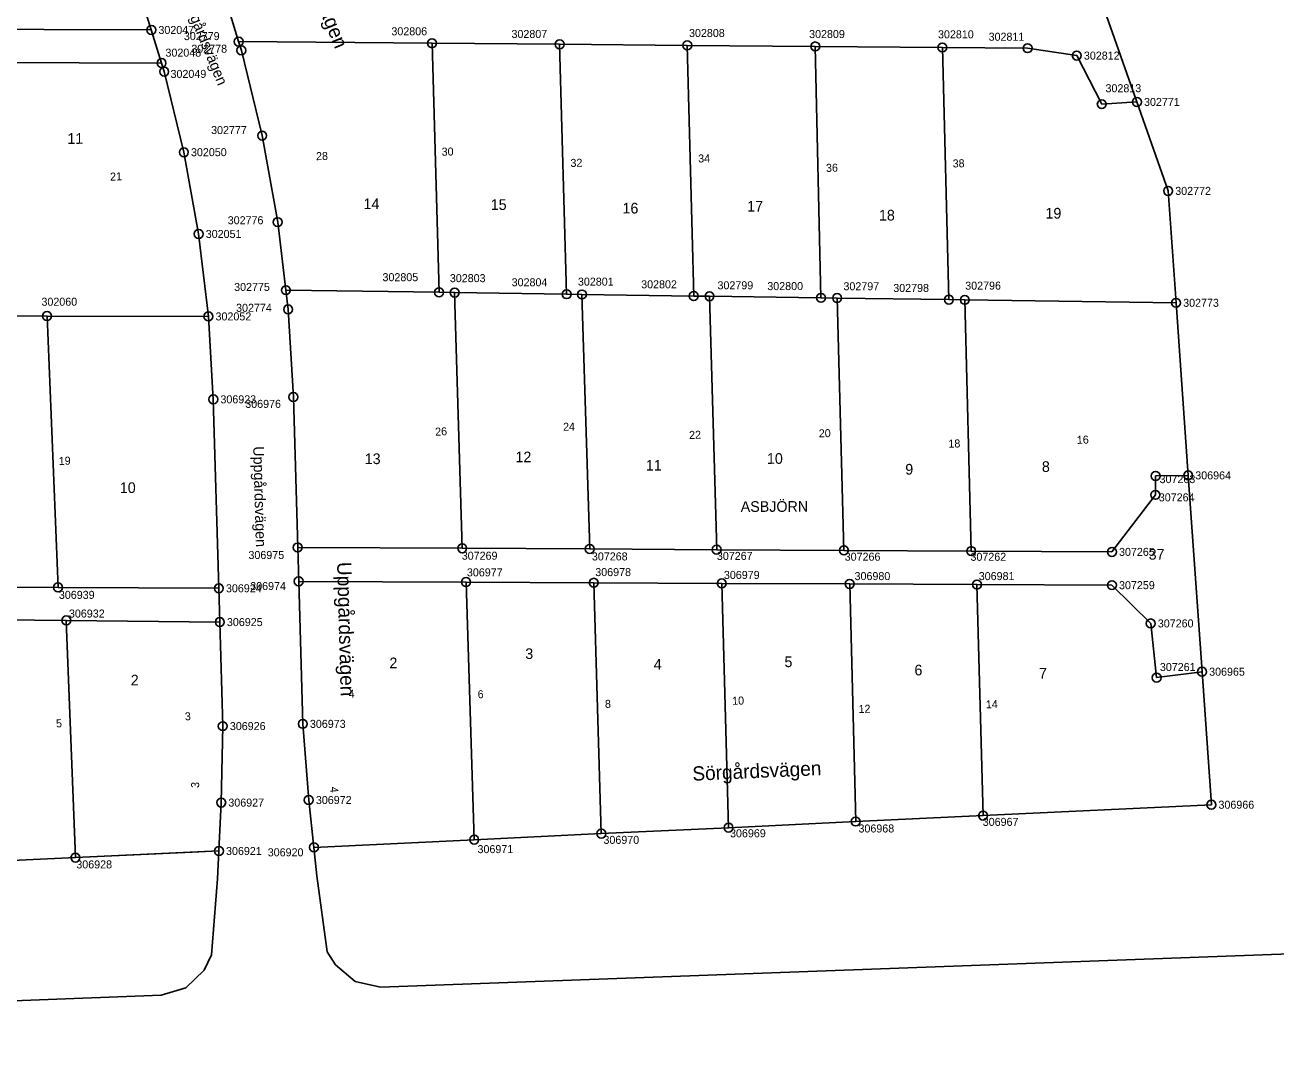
# Model space of a CAD drawing. Extents: x 141995 to 152570, y 6580184 to 6586000.
# Drawn here: x 142587.1 to 142727.8, y 6585369.2 to 6585483.5 of the extents above; entities that cross this region are included whole.
import ezdxf

# ---------------------------------------------------------------- set-up
doc = ezdxf.new("R2010")
doc.units = 0
for name, color, linetype in [('Level 10', 7, 'Continuous'), ('Level 13', 7, 'Continuous'), ('Level 40', 7, 'Continuous'), ('Level 42', 7, 'Continuous'), ('Level 43', 7, 'Continuous'), ('Level 5', 7, 'Continuous'), ('Level 51', 7, 'Continuous'), ('Level 53', 7, 'Continuous'), ('Level 54', 7, 'Continuous'), ('Level 55', 7, 'Continuous'), ('Level 58', 7, 'Continuous'), ('Level 6', 7, 'Continuous'), ('Level 7', 7, 'Continuous')]:
    doc.layers.add(name, color=color, linetype=linetype)

msp = doc.modelspace()

# ---------------------------------------------------------------- linework, layer by layer
at = {"layer": 'Level 10'}
for centre in [(142601.32, 6585482.97), (142611.14, 6585481.66), (142611.44, 6585480.68), (142632.88, 6585481.48), (142647.22, 6585481.36), (142661.57, 6585481.24), (142675.96, 6585481.12), (142690.25, 6585481), (142699.83, 6585480.92), (142602.47, 6585479.25), (142705.36, 6585480.09), (142602.77, 6585478.29), (142712.12, 6585474.88), (142708.17, 6585474.63), (142613.78, 6585471.09), (142604.98, 6585469.22), (142715.63, 6585464.88), (142615.53, 6585461.37), (142606.64, 6585460.04), (142616.45, 6585453.72), (142633.67, 6585453.48), (142635.42, 6585453.45), (142648.01, 6585453.27), (142649.73, 6585453.24), (142662.3, 6585453.06), (142664.07, 6585453.04), (142676.6, 6585452.86), (142678.42, 6585452.84), (142690.98, 6585452.66), (142692.77, 6585452.63), (142716.52, 6585452.3), (142616.7, 6585451.56), (142589.6, 6585450.81), (142607.74, 6585450.77), (142608.29, 6585441.45), (142617.29, 6585441.71), (142714.22, 6585432.84), (142717.88, 6585432.9), (142714.2, 6585430.71), (142617.78, 6585424.8), (142636.27, 6585424.71), (142650.61, 6585424.63), (142664.88, 6585424.55), (142679.18, 6585424.47), (142693.49, 6585424.39), (142709.31, 6585424.3), (142590.83, 6585420.31), (142608.91, 6585420.21), (142617.89, 6585420.99), (142636.7, 6585420.91), (142651.06, 6585420.83), (142665.45, 6585420.76), (142679.83, 6585420.7), (142694.14, 6585420.63), (142709.31, 6585420.56), (142591.76, 6585416.6), (142609.02, 6585416.41), (142713.67, 6585416.26), (142714.33, 6585410.17), (142719.44, 6585410.83), (142609.35, 6585404.71), (142618.35, 6585404.97), (142609.18, 6585396.12), (142619.02, 6585396.41), (142694.83, 6585394.66), (142720.49, 6585395.88), (142666.21, 6585393.3), (142680.51, 6585393.99), (142637.62, 6585391.95), (142651.91, 6585392.63), (142608.92, 6585390.68), (142619.6, 6585391.09), (142592.79, 6585389.94)]:
    msp.add_circle(centre, 0.5, dxfattribs=at)
at = {"layer": 'Level 13'}
for points in [[(142619.94, 6585387.87), (142619.6, 6585391.09)], [(142608.92, 6585390.68), (142608.77, 6585387.55)], [(142608.77, 6585387.55), (142608.1, 6585378.99)], [(142621.1, 6585379.36), (142619.94, 6585387.87)], [(142861.17, 6585383.96), (142627.09, 6585375.39)], [(142608.1, 6585378.99), (142607.27, 6585377.27)], [(142622.01, 6585377.88), (142621.1, 6585379.36)], [(142607.27, 6585377.27), (142605.19, 6585375.28)], [(142624.24, 6585376), (142622.01, 6585377.88)], [(142627.09, 6585375.39), (142624.24, 6585376)], [(142465.66, 6585369.21), (142602.42, 6585374.48)], [(142605.19, 6585375.28), (142602.42, 6585374.48)]]:
    msp.add_lwpolyline(points, dxfattribs=at)
at = {"layer": 'Level 5'}
for points in [[(142705.08, 6585494.89), (142712.12, 6585474.88)], [(142600.01, 6585487.21), (142601.32, 6585482.97)], [(142611.14, 6585481.66), (142609.98, 6585485.4)], [(142601.32, 6585482.97), (142602.47, 6585479.25)], [(142611.44, 6585480.68), (142611.14, 6585481.66)], [(142613.78, 6585471.09), (142611.44, 6585480.68)], [(142602.47, 6585479.25), (142602.77, 6585478.29)], [(142602.77, 6585478.29), (142604.98, 6585469.22)], [(142712.12, 6585474.88), (142715.63, 6585464.88)], [(142615.53, 6585461.37), (142613.78, 6585471.09)], [(142604.98, 6585469.22), (142606.64, 6585460.04)], [(142715.63, 6585464.88), (142716.52, 6585452.3)], [(142616.45, 6585453.72), (142615.53, 6585461.37)], [(142606.64, 6585460.04), (142607.74, 6585450.77)], [(142616.7, 6585451.56), (142616.45, 6585453.72)], [(142616.7, 6585451.56), (142617.29, 6585441.71)], [(142716.52, 6585452.3), (142717.88, 6585432.9)], [(142607.74, 6585450.77), (142608.29, 6585441.45)], [(142617.78, 6585424.8), (142617.29, 6585441.71)], [(142608.29, 6585441.45), (142608.91, 6585420.21)], [(142717.88, 6585432.9), (142719.44, 6585410.83)], [(142617.89, 6585420.99), (142617.78, 6585424.8)], [(142618.35, 6585404.97), (142617.89, 6585420.99)], [(142608.91, 6585420.21), (142609.02, 6585416.41)], [(142609.02, 6585416.41), (142609.35, 6585404.71)], [(142719.44, 6585410.83), (142720.49, 6585395.88)], [(142619.02, 6585396.41), (142618.35, 6585404.97)], [(142609.35, 6585404.71), (142609.18, 6585396.12)], [(142609.18, 6585396.12), (142608.92, 6585390.68)], [(142619.6, 6585391.09), (142619.02, 6585396.41)], [(142720.49, 6585395.88), (142694.83, 6585394.66)], [(142680.51, 6585393.99), (142666.21, 6585393.3)], [(142694.83, 6585394.66), (142680.51, 6585393.99)], [(142651.91, 6585392.63), (142637.62, 6585391.95)], [(142666.21, 6585393.3), (142651.91, 6585392.63)], [(142637.62, 6585391.95), (142619.6, 6585391.09)], [(142592.79, 6585389.94), (142578.51, 6585389.28)], [(142605.91, 6585390.54), (142592.79, 6585389.94)], [(142608.92, 6585390.68), (142605.91, 6585390.54)]]:
    msp.add_lwpolyline(points, dxfattribs=at)
at = {"layer": 'Level 6'}
for points in [[(142578.51, 6585389.28), (142592.79, 6585389.94), (142608.92, 6585390.68), (142609.18, 6585396.12), (142609.35, 6585404.71), (142609.02, 6585416.41), (142608.91, 6585420.21), (142608.29, 6585441.45), (142607.74, 6585450.77), (142606.64, 6585460.04), (142604.98, 6585469.22), (142602.77, 6585478.29), (142602.47, 6585479.25), (142601.32, 6585482.97), (142600.01, 6585487.21), (142593.41, 6585506.56), (142592.02, 6585511.22), (142590.98, 6585515.96), (142590.29, 6585520.78), (142589.98, 6585525.63), (142589.6, 6585539.26), (142589.48, 6585543.81), (142588.35, 6585585.21), (142570.02, 6585584.39)], [(142609.98, 6585485.4), (142611.14, 6585481.66), (142611.44, 6585480.68), (142613.78, 6585471.09), (142615.53, 6585461.37), (142616.45, 6585453.72), (142616.7, 6585451.56), (142617.29, 6585441.71), (142617.78, 6585424.8), (142617.89, 6585420.99), (142618.35, 6585404.97), (142619.02, 6585396.41), (142619.6, 6585391.09), (142637.62, 6585391.95), (142651.91, 6585392.63), (142666.21, 6585393.3), (142680.51, 6585393.99), (142694.83, 6585394.66), (142720.49, 6585395.88), (142719.44, 6585410.83), (142717.88, 6585432.9), (142716.52, 6585452.3), (142715.63, 6585464.88), (142712.12, 6585474.88), (142705.08, 6585494.89)]]:
    msp.add_lwpolyline(points, dxfattribs=at)
at = {"layer": 'Level 7'}
for points in [[(142601.32, 6585482.97), (142577.15, 6585483.05)], [(142611.14, 6585481.66), (142632.88, 6585481.48)], [(142632.88, 6585481.48), (142633.67, 6585453.48)], [(142632.88, 6585481.48), (142647.22, 6585481.36)], [(142647.22, 6585481.36), (142648.01, 6585453.27)], [(142647.22, 6585481.36), (142661.57, 6585481.24)], [(142661.57, 6585481.24), (142662.3, 6585453.06)], [(142661.57, 6585481.24), (142675.96, 6585481.12)], [(142675.96, 6585481.12), (142676.6, 6585452.86)], [(142675.96, 6585481.12), (142690.25, 6585481)], [(142690.25, 6585481), (142690.98, 6585452.66)], [(142690.25, 6585481), (142699.83, 6585480.92)], [(142699.83, 6585480.92), (142705.36, 6585480.09)], [(142705.36, 6585480.09), (142708.17, 6585474.63)], [(142583.93, 6585479.33), (142602.47, 6585479.25)], [(142708.17, 6585474.63), (142712.12, 6585474.88)], [(142616.45, 6585453.72), (142633.67, 6585453.48)], [(142633.67, 6585453.48), (142635.42, 6585453.45)], [(142635.42, 6585453.45), (142648.01, 6585453.27)], [(142635.42, 6585453.45), (142636.27, 6585424.71)], [(142648.01, 6585453.27), (142649.73, 6585453.24)], [(142649.73, 6585453.24), (142662.3, 6585453.06)], [(142649.73, 6585453.24), (142650.61, 6585424.63)], [(142662.3, 6585453.06), (142664.07, 6585453.04)], [(142664.07, 6585453.04), (142676.6, 6585452.86)], [(142664.07, 6585453.04), (142664.88, 6585424.55)], [(142676.6, 6585452.86), (142678.42, 6585452.84)], [(142678.42, 6585452.84), (142690.98, 6585452.66)], [(142678.42, 6585452.84), (142679.18, 6585424.47)], [(142690.98, 6585452.66), (142692.77, 6585452.63)], [(142692.77, 6585452.63), (142716.52, 6585452.3)], [(142692.77, 6585452.63), (142693.49, 6585424.39)], [(142584.99, 6585450.82), (142589.6, 6585450.81)], [(142589.6, 6585450.81), (142607.74, 6585450.77)], [(142589.6, 6585450.81), (142590.83, 6585420.31)], [(142714.22, 6585432.84), (142714.2, 6585430.71)], [(142717.88, 6585432.9), (142714.22, 6585432.84)], [(142714.2, 6585430.71), (142709.31, 6585424.3)], [(142636.27, 6585424.71), (142617.78, 6585424.8)], [(142650.61, 6585424.63), (142636.27, 6585424.71)], [(142664.88, 6585424.55), (142650.61, 6585424.63)], [(142679.18, 6585424.47), (142664.88, 6585424.55)], [(142693.49, 6585424.39), (142679.18, 6585424.47)], [(142709.31, 6585424.3), (142693.49, 6585424.39)], [(142590.83, 6585420.31), (142576.47, 6585420.39)], [(142617.89, 6585420.99), (142636.7, 6585420.91)], [(142636.7, 6585420.91), (142637.62, 6585391.95)], [(142636.7, 6585420.91), (142651.06, 6585420.83)], [(142651.06, 6585420.83), (142651.91, 6585392.63)], [(142651.06, 6585420.83), (142665.45, 6585420.76)], [(142665.45, 6585420.76), (142666.21, 6585393.3)], [(142665.45, 6585420.76), (142679.83, 6585420.7)], [(142679.83, 6585420.7), (142680.51, 6585393.99)], [(142679.83, 6585420.7), (142694.14, 6585420.63)], [(142694.14, 6585420.63), (142709.31, 6585420.56)], [(142694.14, 6585420.63), (142694.83, 6585394.66)], [(142709.31, 6585420.56), (142713.67, 6585416.26)], [(142608.91, 6585420.21), (142590.83, 6585420.31)], [(142577.43, 6585416.75), (142591.76, 6585416.6)], [(142592.79, 6585389.94), (142591.76, 6585416.6)], [(142591.76, 6585416.6), (142609.02, 6585416.41)], [(142713.67, 6585416.26), (142714.33, 6585410.17)], [(142714.33, 6585410.17), (142719.44, 6585410.83)]]:
    msp.add_lwpolyline(points, dxfattribs=at)

# ---------------------------------------------------------------- texts
at = {"layer": 'Level 40'}
msp.add_text('Uppgårdsvägen', height=1.2, rotation=292.254, dxfattribs=at).set_placement((142604.54, 6585487.11))
at = {"layer": 'Level 42'}
msp.add_text('Uppgårdsvägen', height=1.2, rotation=271.5482, dxfattribs=at).set_placement((142612.77, 6585436.16))
at = {"layer": 'Level 43'}
for s, rotation, p in [('Uppgårdsvägen', 292.2522, (142616.29, 6585494.73)), ('Uppgårdsvägen', 271.5482, (142622.2, 6585423.15)), ('Sörgårdsvägen', 2.5359, (142662.18, 6585398.57))]:
    msp.add_text(s, height=1.6, rotation=rotation, dxfattribs=at).set_placement(p)
at = {"layer": 'Level 51'}
for s, rotation, p in [('11', 0.0577, (142591.88, 6585470.17)), ('14', 0.0451, (142625.18, 6585462.83)), ('15', 0.0451, (142639.48, 6585462.74)), ('16', 0.0485, (142654.29, 6585462.34)), ('17', 0.0485, (142668.31, 6585462.56)), ('18', 0.0485, (142683.12, 6585461.55)), ('19', 0.0485, (142701.84, 6585461.77)), ('13', 0.0451, (142625.31, 6585434.17)), ('12', 0.0485, (142642.26, 6585434.37)), ('11', 0.0485, (142656.92, 6585433.44)), ('10', 0.0485, (142670.53, 6585434.2)), ('8', 0.0485, (142701.44, 6585433.29)), ('9', 0.0485, (142686.08, 6585432.99)), ('10', 0.0527, (142597.78, 6585430.92)), ('37', 0.049, (142713.44, 6585423.43)), ('3', 0.0485, (142643.36, 6585412.26)), ('2', 0.0522, (142628.09, 6585411.22)), ('4', 0.0485, (142657.8, 6585411.05)), ('5', 0.0485, (142672.5, 6585411.35)), ('6', 0.049, (142687.11, 6585410.42)), ('7', 0.049, (142701.11, 6585410.05)), ('2', 0.0527, (142599.01, 6585409.29))]:
    msp.add_text(s, height=1.2, rotation=rotation, dxfattribs=at).set_placement(p)
at = {"layer": 'Level 53'}
for s, rotation, p in [('302047', 0.0577, (142602.12, 6585482.52)), ('302779', 0.0451, (142604.98, 6585481.83)), ('302806', 0.0451, (142628.31, 6585482.37)), ('302807', 0.0485, (142641.81, 6585482.07)), ('302808', 0.0485, (142661.77, 6585482.18)), ('302809', 0.0485, (142675.27, 6585482.06)), ('302810', 0.0485, (142689.76, 6585482.03)), ('302811', 0.0485, (142695.45, 6585481.76)), ('302048', 0.0577, (142602.91, 6585479.97)), ('302778', 0.0451, (142605.82, 6585480.41)), ('302812', 0.0485, (142706.16, 6585479.64)), ('302049', 0.0577, (142603.48, 6585477.58)), ('302813', 0.0485, (142708.59, 6585475.97)), ('302771', 0.0485, (142712.92, 6585474.43)), ('302777', 0.0451, (142608.04, 6585471.27)), ('302050', 0.0577, (142605.78, 6585468.78)), ('302772', 0.0485, (142716.43, 6585464.43)), ('302776', 0.051, (142609.91, 6585461.13)), ('302051', 0.0577, (142607.44, 6585459.59)), ('302805', 0.0451, (142627.31, 6585454.73)), ('302775', 0.0577, (142610.63, 6585453.63)), ('302803', 0.0451, (142634.88, 6585454.62)), ('302804', 0.0485, (142641.83, 6585454.16)), ('302801', 0.0485, (142649.28, 6585454.23)), ('302802', 0.0485, (142656.39, 6585453.93)), ('302799', 0.0485, (142664.97, 6585453.82)), ('302800', 0.0485, (142670.57, 6585453.73)), ('302797', 0.0485, (142679.13, 6585453.71)), ('302798', 0.0485, (142684.73, 6585453.52)), ('302796', 0.0485, (142692.82, 6585453.78)), ('302060', 0.0527, (142588.97, 6585451.97)), ('302773', 0.0485, (142717.32, 6585451.85)), ('302774', 0.0577, (142610.85, 6585451.29)), ('302052', 0.0577, (142608.54, 6585450.32)), ('306923', 0.0577, (142609.09, 6585441)), ('306976', 0.0577, (142611.88, 6585440.49)), ('306964', 0.049, (142718.68, 6585432.45)), ('307263', 0.049, (142714.67, 6585432.03)), ('307264', 0.049, (142714.58, 6585429.98)), ('307265', 0.049, (142710.11, 6585423.85)), ('306975', 0.0577, (142612.24, 6585423.5)), ('307269', 0.0451, (142636.22, 6585423.42)), ('307268', 0.0485, (142650.85, 6585423.34)), ('307267', 0.0485, (142664.9, 6585423.4)), ('307266', 0.0485, (142679.27, 6585423.31)), ('307262', 0.0485, (142693.41, 6585423.3)), ('306977', 0.0451, (142636.8, 6585421.55)), ('306978', 0.0485, (142651.23, 6585421.58)), ('306979', 0.0485, (142665.69, 6585421.26)), ('306980', 0.0485, (142680.38, 6585421.13)), ('306981', 0.049, (142694.34, 6585421.13)), ('306924', 0.0527, (142609.71, 6585419.76)), ('306974', 0.0577, (142612.44, 6585420.01)), ('307259', 0.049, (142710.11, 6585420.11)), ('306939', 0.0527, (142590.93, 6585419.02)), ('306932', 0.0527, (142592.06, 6585416.92)), ('306925', 0.0527, (142609.82, 6585415.96)), ('307260', 0.049, (142714.47, 6585415.81)), ('307261', 0.049, (142714.7, 6585410.91)), ('306965', 0.049, (142720.24, 6585410.38)), ('306926', 0.0527, (142610.15, 6585404.27)), ('306973', 0.0527, (142619.15, 6585404.52)), ('306927', 0.0527, (142609.98, 6585395.67)), ('306972', 0.0527, (142619.82, 6585395.96)), ('306966', 0.049, (142721.29, 6585395.43)), ('306968', 0.049, (142680.82, 6585392.76)), ('306967', 0.049, (142694.79, 6585393.5)), ('306970', 0.0485, (142652.15, 6585391.48)), ('306969', 0.049, (142666.38, 6585392.22)), ('306921', 0.0527, (142609.72, 6585390.23)), ('306920', 0.0527, (142614.41, 6585390.08)), ('306971', 0.0455, (142637.99, 6585390.44)), ('306928', 0.0527, (142592.89, 6585388.72))]:
    msp.add_text(s, height=0.9, rotation=rotation, dxfattribs=at).set_placement(p)
at = {"layer": 'Level 54'}
for s, rotation, p in [('30', 1.53, (142633.97, 6585468.83)), ('28', 1.536, (142619.85, 6585468.33)), ('32', 1.5356, (142648.45, 6585467.57)), ('34', 1.5476, (142662.81, 6585468.07)), ('38', 1.5886, (142691.42, 6585467.51)), ('21', 2.2257, (142596.7, 6585466.03)), ('36', 1.6516, (142677.18, 6585467.01)), ('24', 1.6606, (142647.62, 6585437.91)), ('26', 3.115, (142633.25, 6585437.35)), ('22', 1.8377, (142661.79, 6585436.99)), ('20', 1.7096, (142676.37, 6585437.17)), ('16', 1.8337, (142705.38, 6585436.44)), ('18', 1.6806, (142690.94, 6585436.01)), ('19', 1.9837, (142590.93, 6585434.07)), ('4', 1.6767, (142623.51, 6585407.91)), ('6', 1.725, (142638.02, 6585407.84)), ('10', 1.6126, (142666.63, 6585407.11)), ('8', 1.7266, (142652.33, 6585406.76)), ('12', 1.6231, (142680.84, 6585406.19)), ('14', 1.6671, (142695.15, 6585406.71)), ('5', 2.1617, (142590.62, 6585404.57)), ('3', 2.5137, (142605.11, 6585405.36))]:
    msp.add_text(s, height=0.9, rotation=rotation, dxfattribs=at).set_placement(p)
at = {"layer": 'Level 55'}
for s, rotation, p in [('3', 88.8503, (142606.69, 6585397.76)), ('4', 274.4593, (142621.42, 6585397.87))]:
    msp.add_text(s, height=0.9, rotation=rotation, dxfattribs=at).set_placement(p)
at = {"layer": 'Level 58'}
msp.add_text('ASBJÖRN', height=1.2, rotation=0.0485, dxfattribs=at).set_placement((142667.58, 6585428.8))

doc.saveas('drawing.dxf')
